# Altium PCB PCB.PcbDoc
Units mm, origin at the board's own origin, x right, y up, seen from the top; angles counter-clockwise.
Board outline 107.6 x 53.34 mm, 4 copper layers (TOP, INNER1, INNER2, BOTTOM), stack 1.569 mm thick; 10 components, 91 nets, 221 pads, 142 vias.
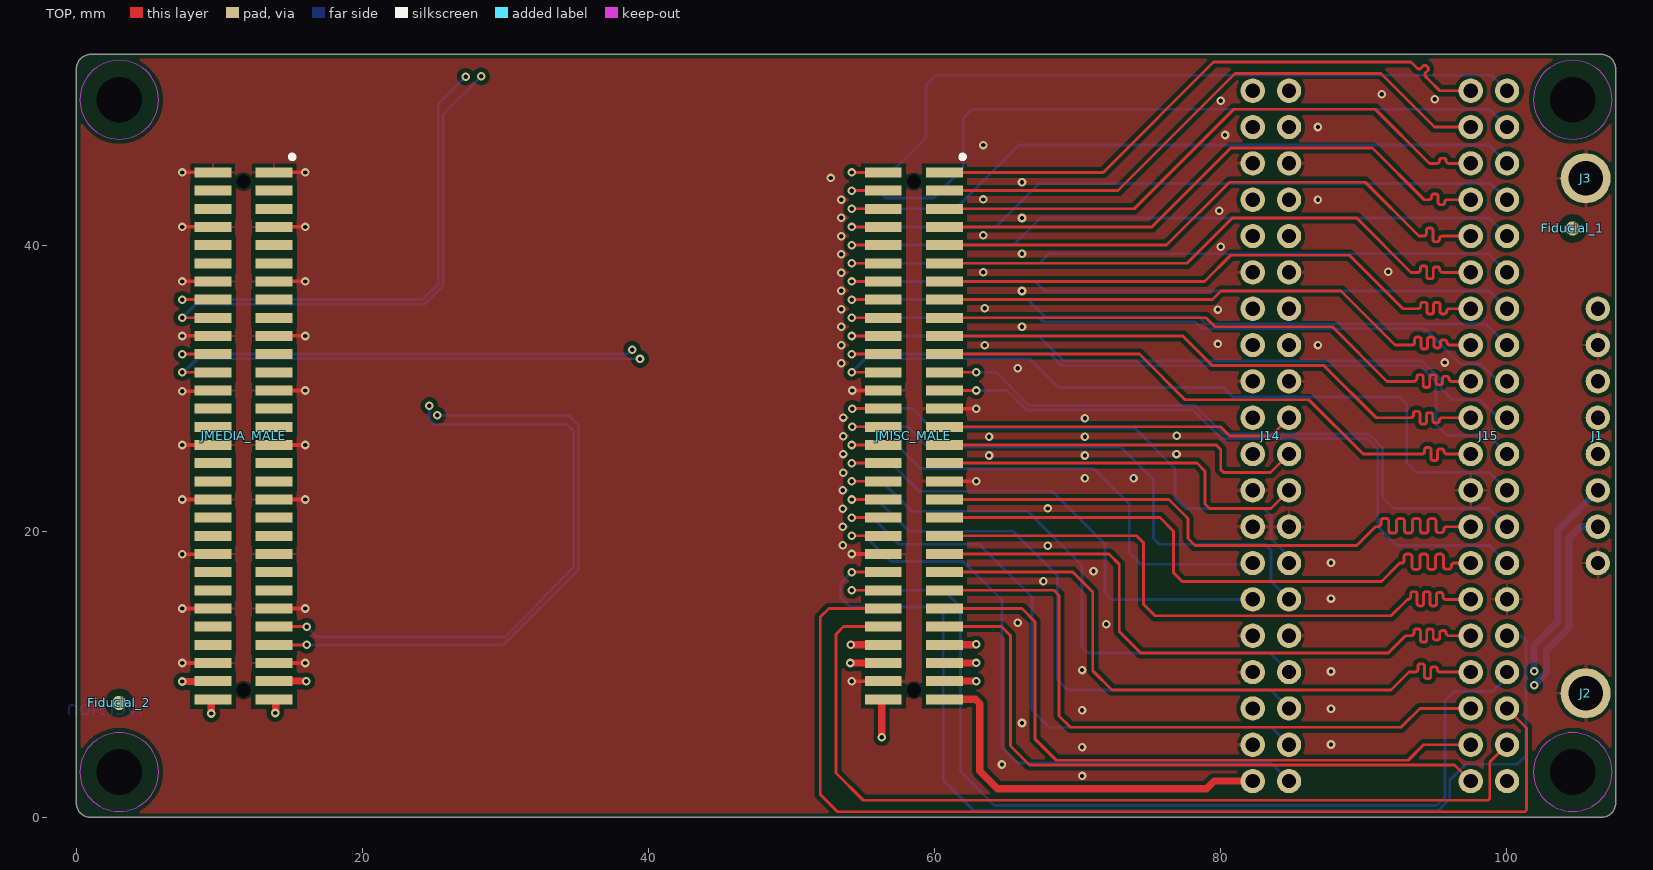
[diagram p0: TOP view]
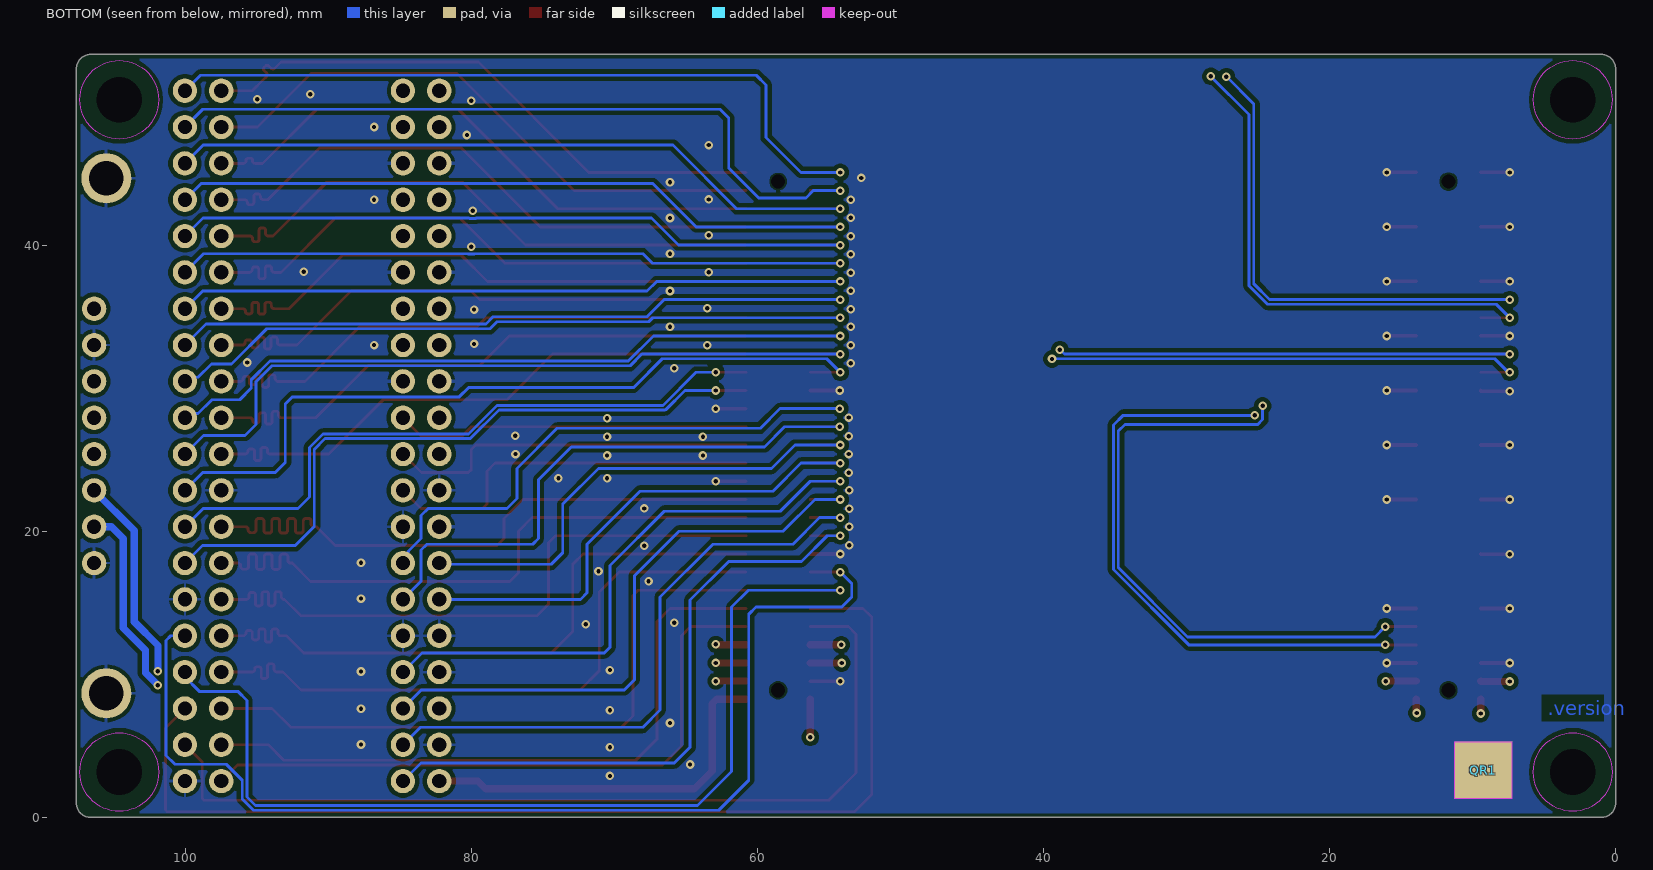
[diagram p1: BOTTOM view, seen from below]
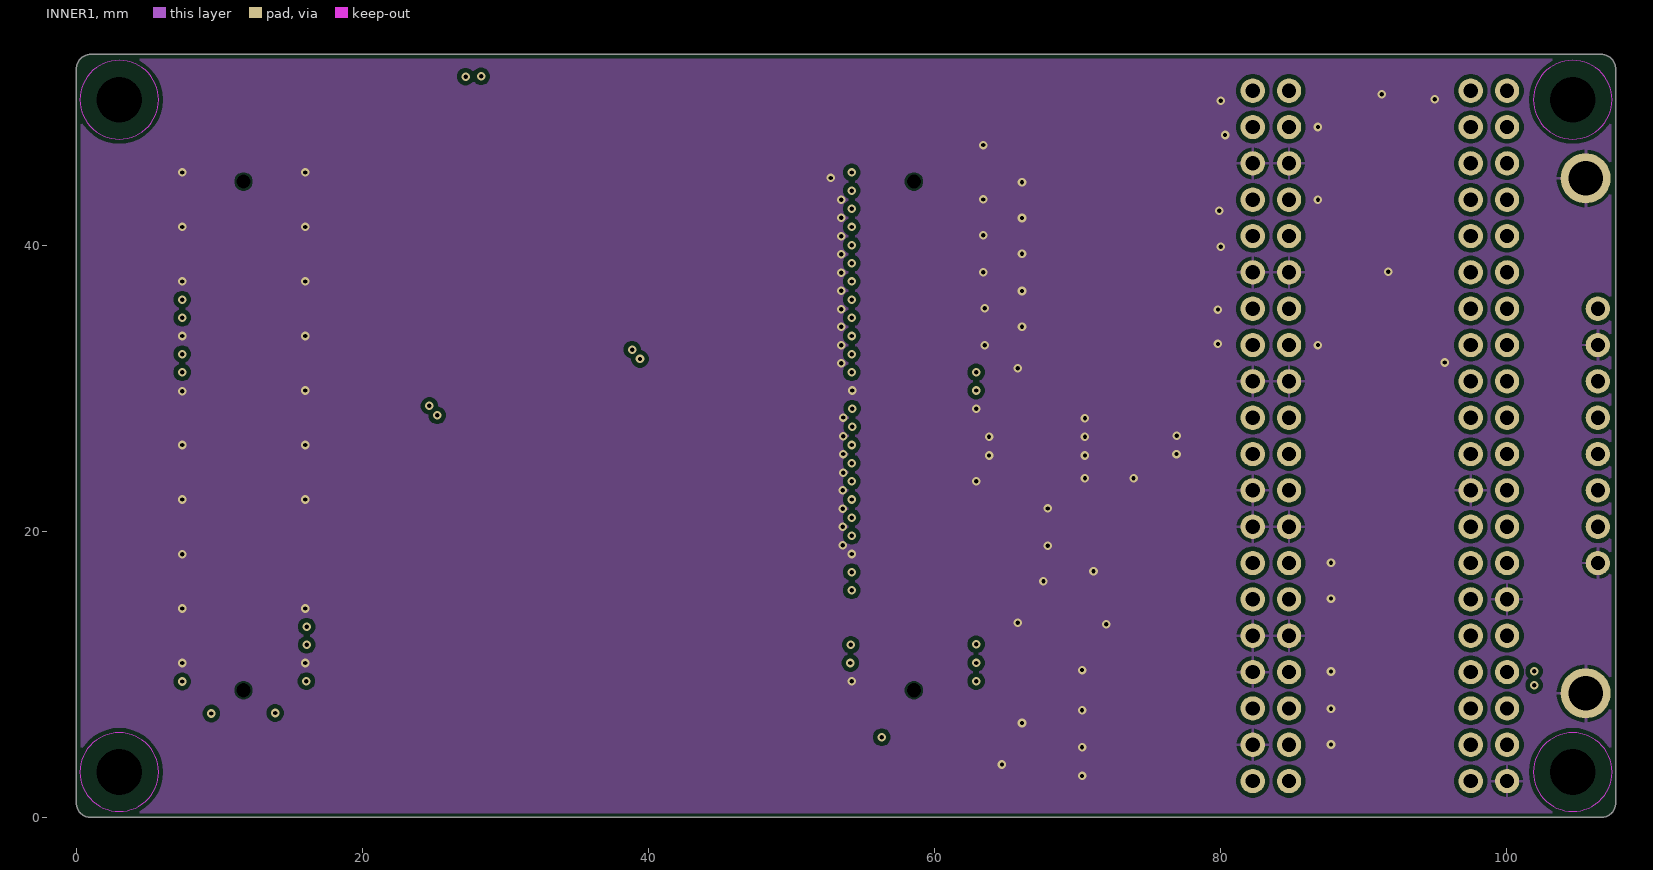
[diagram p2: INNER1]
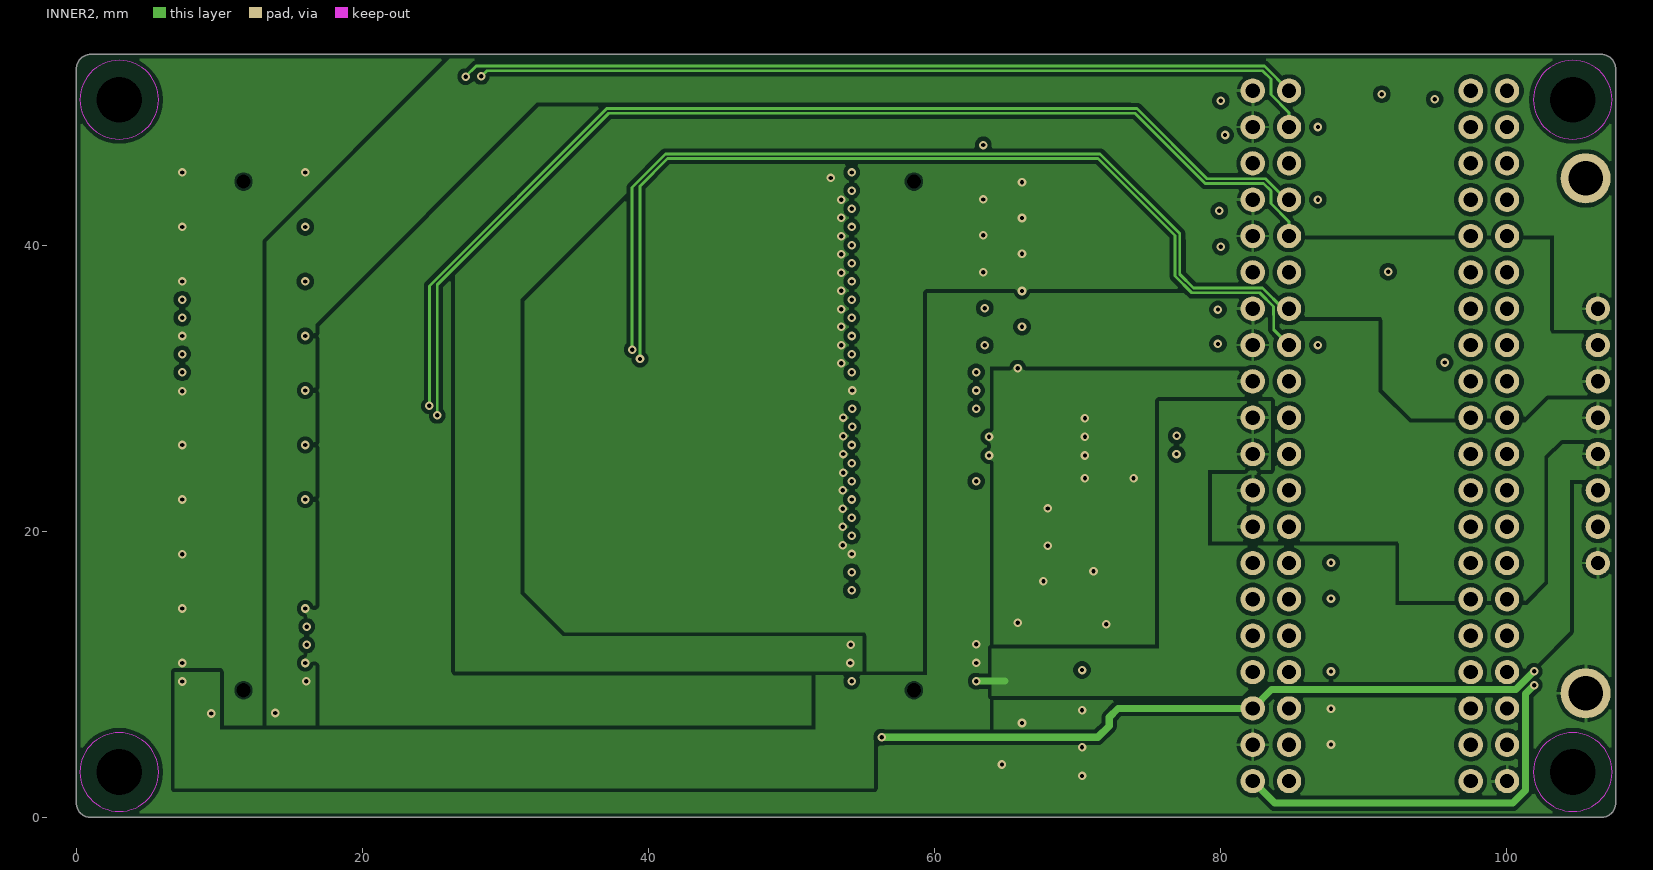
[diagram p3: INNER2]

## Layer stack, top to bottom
Top Solder: solder mask 0.0254, SM-003, Dk 4
TOP: signal copper 0.035
Dielectric 1: prepreg 0.0994, PP-014, Dk 4.2
INNER1: signal copper 0.0175
Dielectric2: core 1.265, FR-4, Dk 4.8
INNER2: signal copper 0.0175
Dielectric3: prepreg 0.0994, PP-014, Dk 4.2
BOTTOM: signal copper 0.035
Bottom Solder: solder mask 0.0254, SM-003, Dk 4

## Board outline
0,1 0,52.34 cw(c1,52.34) 1,53.34 106.6,53.34 cw(c106.6,52.34) 107.6,52.34 107.6,1 cw(c106.6,1) 106.6,0 1,0 cw(c1,1)

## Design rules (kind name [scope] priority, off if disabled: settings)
BoardOutlineClearance Silks [(OnLayer('Top Overlay') OR OnLayer('Bottom Overlay'))] p1: gap=0 ignorepadtopadclearanceinfootprint=FALSE
BoardOutlineClearance [All] p2: gap=0.3 ignorepadtopadclearanceinfootprint=FALSE
Clearance COPPER_0.3mm [All] p1: gap=0.127 ignorepadtopadclearanceinfootprint=FALSE except(0.3: Arc-Fill Arc-Poly Arc-Region Track-Fill Track-Poly Track-Region SMDPad-Fill SMDPad-Poly SMDPad-Region THPad-Fill THPad-Poly THPad-Region Via-Fill Via-Poly Via-Region Fill-Fill Fill-Poly Fill-Region Poly-Poly Poly-Region Region-Region)
Clearance "Generic clearance 0.127mm" [All] p2: gap=0.127 ignorepadtopadclearanceinfootprint=FALSE
ComponentClearance [All] p1: gap=0.2 collisioncheckmode=3 verticalgap=0 showdistances=TRUE
DiffPairsRouting DSI_100R [InDifferentialPairClass('DSI')] p1: maxlimit=0.36 minlimit=0.21 mostfreqgap=0.36 toplayer_maxgap=0.21 toplayer_prefgap=0.21 toplayer_minwidth=0.18 toplayer_maxwidth=0.18 toplayer_prefwidth=0.18 midlayer1_mingap=0.36 midlayer1_minwidth=0.127 midlayer1_maxwidth=0.127 midlayer1_prefwidth=0.127 midlayer2_mingap=0.36 midlayer2_minwidth=0.127 midlayer2_maxwidth=0.127 midlayer2_prefwidth=0.127 bottomlayer_maxgap=0.21 bottomlayer_prefgap=0.21 bottomlayer_minwidth=0.18 bottomlayer_maxwidth=0.18 bottomlayer_prefwidth=0.18 impedanceprofiledriven=TRUE impedanceprofileid={F22B831B-72FA-4BC6-B015-EECE9AC290C8} impedanceprofilevalue=100.000000 maxuncoupledlength=12.7
Height [All] p1: minheight=0 maxheight=30 prefheight=12.7
HoleSize [All] p1: absolutevalues=TRUE maxlimit=30 minlimit=0.3 maxpercent=80.000 minpercent=20.000
HoleToHoleClearance [All] p1: gap=0.25 allowstackedmicrovias=FALSE
MatchedLengths MatchedLengths_SE0 [InNetClass('SE0_Lines')] p1: tolerance=0.15 checknetsindiffpair=FALSE checkdiffpairvsdiffpair=TRUE checkxsignals=TRUE checkothers=TRUE
MatchedLengths MatchedLengths_PSSI [InNetClass('PSSI_Lines')] p2: tolerance=0.15 checknetsindiffpair=FALSE checkdiffpairvsdiffpair=TRUE checkxsignals=TRUE checkothers=TRUE
MatchedLengths DSI_delay_pairs [InDifferentialPairClass('DSI')] p3: tolerance=25.4 checknetsindiffpair=TRUE checkdiffpairvsdiffpair=FALSE checkxsignals=FALSE checkothers=FALSE usedelayunits=TRUE delaytolerance=5.000000
MatchedLengths DSI_delay_group [InDifferentialPairClass('DSI')] p4: tolerance=25.4 checknetsindiffpair=FALSE checkdiffpairvsdiffpair=TRUE checkxsignals=TRUE checkothers=TRUE usedelayunits=TRUE delaytolerance=5.000000
MinimumAnnularRing Fixingpins [(ObjectKind = 'Pad') And (Name = 'Free-FIXING')] p1: minimumring=0
MinimumAnnularRing [All] p2: minimumring=0.15
PlaneConnect [All] p1: pad.planeconnectstyle=Relief pad.reliefexpansion=0.508 pad.reliefentries=4 pad.reliefconductorwidth=0.254 pad.reliefairgap=0.254 via.planeconnectstyle=Direct via.reliefexpansion=0.508 via.reliefentries=4 via.reliefconductorwidth=0.254 via.reliefairgap=0.254
PolygonConnect QR_POLY [(ObjectKind = 'Pad') And (Name = 'QR1-PAD')] p1: connectstyle=Direct reliefconductorwidth=0.254 reliefentries=4 polygonreliefangle="90 Angle" airgapwidth=0.254
PolygonConnect [All] p2: thpad.connectstyle=Relief thpad.reliefconductorwidth=0.2 thpad.reliefentries=4 thpad.polygonreliefangle="90 Angle" thpad.airgapwidth=0.254 smdpad.connectstyle=Relief smdpad.reliefconductorwidth=0.2 smdpad.reliefentries=4 smdpad.polygonreliefangle="90 Angle" smdpad.airgapwidth=0.254 via.connectstyle=Direct via.reliefconductorwidth=0.254 via.reliefentries=4 via.polygonreliefangle="90 Angle" via.airgapwidth=0.254
ReturnPath ReturnPath_100R [InNetClass('IMPEDANCE_100R')] p1: impedanceprofileid={A0C224CA-506F-4870-9C4E-CE84658735AE} _gaplimit=0 _useantipads=TRUE maxstitchviadistance=1.5
RoutingVias StandardVias [All] p1: holewidth=0.3 width=0.6 viastyle="Through Hole" minholewidth=0.3 minwidth=0.6 maxholewidth=0.3 maxwidth=0.6
SMDToCorner [All] p1: distance=39370
SilkToSilkClearance [All] p1: silktosilkclearance=0.2
SilkToSolderMaskClearance [IsPad] p1: minsilkscreentomaskgap=0.15 clearancetoexposedcopper=TRUE
SolderMaskExpansion VIAtented [IsVia] p1: expansion=0.102 istentingtop=TRUE
SolderMaskExpansion [All] p2: expansion=0.05 istentingtop=FALSE
SupplyNets "Schematic Supply Nets_1" [InNet('+5V')] p1: voltage=0.000
SupplyNets "Schematic Supply Nets_5" [InNet('PWR_3P3V')] p2: voltage=0.000
SupplyNets "Schematic Supply Nets_4" [InNet('DC_IN')] p3: voltage=0.000
SupplyNets "Schematic Supply Nets" [InNet('VCC_PX3_1P8')] p4: voltage=0.000
SupplyNets "Schematic Supply Nets_7" [InNet('VCOIN')] p5: voltage=0.000
SupplyNets "Schematic Supply Nets_3" [InNet('VBAT')] p6: voltage=0.000
SupplyNets "Schematic Supply Nets_2" [InNet('GND')] p7: voltage=0.000
UnConnectedPin [All] p1:
UnRoutedNet [All] p1: checkbadconnections=TRUE
ViasUnderSMD [All] p1: allowed=FALSE
Width StandardTraces [All] p1: maxlimit=5 minlimit=0.127 preferedwidth=0.15
21 further rules are at their usual default settings.

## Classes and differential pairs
net class SE0_Lines: NetJ15_25 NetJ15_27 NetJ15_29 NetJ15_31 NetJ15_33 NetJ15_35
net class PSSI_Lines: NetJ15_1 NetJ15_3 NetJ15_5 NetJ15_7 NetJ15_9 NetJ15_11 NetJ15_13 NetJ15_15 NetJ15_17 NetJ15_19 NetJ15_21
component class U_HEADERS: J1 J14 J15
differential pair class DSI: DSI_CLK DSI_D0 DSI_D1 DSI_D2 DSI_D3
component class U_HEADERS_IMOLA_MALE: JMEDIA_MALE JMISC_MALE
differential pair class CSI1: CSI0_CK CSI0_D0 CSI0_D1 CSI0_D2 CSI0_D3
differential pair class CSI0: CSI1_CK CSI1_D0 CSI1_D1 CSI1_D2 CSI1_D3
net class IMPEDANCE_100R: CSI0_CK_N CSI0_CK_P CSI0_D0_N CSI0_D0_P CSI0_D1_N CSI0_D1_P CSI0_D2_N CSI0_D2_P CSI0_D3_N CSI0_D3_P CSI1_CK_N CSI1_CK_P CSI1_D0_N CSI1_D0_P CSI1_D1_N CSI1_D1_P CSI1_D2_N CSI1_D2_P CSI1_D3_N CSI1_D3_P DSI_CLK_N DSI_CLK_P DSI_D0_N DSI_D0_P DSI_D1_N DSI_D1_P DSI_D2_N DSI_D2_P DSI_D3_N DSI_D3_P
component class TOP: Fiducial_1 Fiducial_2 J2 J3 QR1
differential pair DSI_D3: +DSI_D3_P -DSI_D3_N
differential pair DSI_D2: +DSI_D0_P -DSI_D0_N
differential pair DSI_D1: +DSI_CLK_P -DSI_CLK_N
differential pair DSI_D0: +DSI_D2_P -DSI_D2_N
differential pair DSI_CLK: +DSI_D1_P -DSI_D1_N
differential pair CSI1_D3: +CSI0_D1_P -CSI0_D1_N
differential pair CSI1_D2: +CSI0_CK_P -CSI0_CK_N
differential pair CSI1_D1: +CSI0_D3_P -CSI0_D3_N
differential pair CSI1_D0: +CSI1_D0_P -CSI1_D0_N
differential pair CSI1_CK: +CSI0_D2_P -CSI0_D2_N
differential pair CSI0_D3: +CSI1_D1_P -CSI1_D1_N
differential pair CSI0_D2: +CSI1_CK_P -CSI1_CK_N
differential pair CSI0_D1: +CSI1_D3_P -CSI1_D3_N
differential pair CSI0_D0: +CSI0_D0_P -CSI0_D0_N
differential pair CSI0_CK: +CSI1_D2_P -CSI1_D2_N

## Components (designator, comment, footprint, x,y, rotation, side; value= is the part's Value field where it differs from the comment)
Fiducial_1 "Fiducial mark 1mm with 2mm solder" "Fiducial mark 1mm with circle-Footprint-1" 104.6,41.17 r90 top
Fiducial_2 "Fiducial mark 1mm with 2mm solder" "Fiducial mark 1mm with circle-Footprint-1" 3,8 r90 top
J1 "HEADER TH 2.54mm VERT. 1x008POS" "PIN HEADER 2.54mm VERT. 1x8POS" 106.36,26.67 r270 top
J2 "1502-2" 1502-2 105.5,8.67 r0 top
J3 "1502-2" 1502-2 105.5,44.67 r0 top
J14 "PH2-40-UA" "PIN HEADER 2.54mm VERT. 2x20POS" 83.5,26.67 r270 top locked
J15 "PH2-40-UA" "PIN HEADER 2.54mm VERT. 2x20POS" 98.74,26.67 r270 top locked
JMEDIA_MALE "GPEC212-3002A011C1AF" GPEC212-3002A011C1AF 11.684,26.67 r270 top
JMISC_MALE "GPEC212-3002A011C1AF" GPEC212-3002A011C1AF 58.547,26.67 r270 top
QR1 "QR CODE 4x4mm" "QR CODE 4x4mm" 9.25,3.3 r180 bottom locked

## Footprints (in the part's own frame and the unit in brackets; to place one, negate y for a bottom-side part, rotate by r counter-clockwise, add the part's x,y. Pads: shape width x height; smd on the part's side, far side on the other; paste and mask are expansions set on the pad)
1502-2 [mm]
  round 3.5 hole 2.4 paste-2539.97 mask+0.102: 1(0,0)
  body extent -1.58,-1.59 1.58,1.59, height 5.63
"Fiducial mark 1mm with circle-Footprint-1" [mm]
  round 1 smd paste-10 mask+0.5: 1(0,0)
  TOP pour cut-out: 0,1 0.383,0.924 0.707,0.707 0.924,0.383 1,0 1,0 0.924,-0.383 0.707,-0.707 0.383,-0.924 0,-1 0,-1 -0.383,-0.924 -0.707,-0.707 -0.924,-0.383 -1,0 -1,0 -0.924,0.383 -0.707,0.707 -0.383,0.924 0,1
GPEC212-3002A011C1AF [mm]
  rect 0.7x2.57 smd mask+0.1: 1(-18.415,2.135) 2(-18.415,-2.135) 3(-17.145,2.135) 4(-17.145,-2.135) 5(-15.875,2.135) 6(-15.875,-2.135) 7(-14.605,2.135) 8(-14.605,-2.135) 9(-13.335,2.135) 10(-13.335,-2.135) 11(-12.065,2.135) 12(-12.065,-2.135) 13(-10.795,2.135) 14(-10.795,-2.135) 15(-9.525,2.135) 16(-9.525,-2.135) 17(-8.255,2.135) 18(-8.255,-2.135) 19(-6.985,2.135) 20(-6.985,-2.135) 21(-5.715,2.135) 22(-5.715,-2.135) 23(-4.445,2.135) 24(-4.445,-2.135) 25(-3.175,2.135) 26(-3.175,-2.135) 27(-1.905,2.135) 28(-1.905,-2.135) 29(-0.635,2.135) 30(-0.635,-2.135) 31(0.635,2.135) 32(0.635,-2.135) 33(1.905,2.135) 34(1.905,-2.135) 35(3.175,2.135) 36(3.175,-2.135) 37(4.445,2.135) 38(4.445,-2.135) 39(5.715,2.135) 40(5.715,-2.135) 41(6.985,2.135) 42(6.985,-2.135) 43(8.255,2.135) 44(8.255,-2.135) 45(9.525,2.135) 46(9.525,-2.135) 47(10.795,2.135) 48(10.795,-2.135) 49(12.065,2.135) 50(12.065,-2.135) 51(13.335,2.135) 52(13.335,-2.135) 53(14.605,2.135) 54(14.605,-2.135) 55(15.875,2.135) 56(15.875,-2.135) 57(17.145,2.135) 58(17.145,-2.135) 59(18.415,2.135) 60(18.415,-2.135)
  silkscreen extent -19.55,3.35 -19.45,3.45, body extent -19.05,-2.92 19.05,2.92, height 5.97
"PIN HEADER 2.54mm VERT. 1x8POS" [mm]
  round 1.7 hole 1 mask+0.1: 1(-8.89,0) 2(-6.35,0) 3(-3.81,0) 4(-1.27,0) 5(1.27,0) 6(3.81,0) 7(6.35,0) 8(8.89,0)
"PIN HEADER 2.54mm VERT. 2x20POS" [mm]
  round 1.7 hole 1: 1(-24.13,-1.27) 2(-24.13,1.27) 3(-21.59,-1.27) 4(-21.59,1.27) 5(-19.05,-1.27) 6(-19.05,1.27) 7(-16.51,-1.27) 8(-16.51,1.27) 9(-13.97,-1.27) 10(-13.97,1.27) 11(-11.43,-1.27) 12(-11.43,1.27) 13(-8.89,-1.27) 14(-8.89,1.27) 15(-6.35,-1.27) 16(-6.35,1.27) 17(-3.81,-1.27) 18(-3.81,1.27) 19(-1.27,-1.27) 20(-1.27,1.27) 21(1.27,-1.27) 22(1.27,1.27) 23(3.81,-1.27) 24(3.81,1.27) 25(6.35,-1.27) 26(6.35,1.27) 27(8.89,-1.27) 28(8.89,1.27) 29(11.43,-1.27) 30(11.43,1.27) 31(13.97,-1.27) 32(13.97,1.27) 33(16.51,-1.27) 34(16.51,1.27) 35(19.05,-1.27) 36(19.05,1.27) 37(21.59,-1.27) 38(21.59,1.27) 39(24.13,-1.27) 40(24.13,1.27)
  body extent -25.4,-2.54 25.4,2.54, height 9.5
"QR CODE 4x4mm" [mm]
  rect 4x4 smd paste-2539.97 mask+0.1: PAD(0,0)
  TOP keep-out region: -2,2 2,2 2,-2 -2,-2

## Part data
Fiducial_1 Fiducial_2: library part UT0024-A.6
J1: library part J0171-A.4
J2 J3: library part J0379-A.2, "Turret Connector TH 5,56mm lenght", Manufacturer="Keystone Electronics"
J14 J15: library part J0326-A.4, "HEADER TH 2.54mm VERT. MALE 2x20POS", Manufacturer="Adam Tech"
JMEDIA_MALE JMISC_MALE: library part J0568-A.3, "CONN HEADER MALE VERTICAL SMD 1.27mm 2x30 POS lead heigth 3.5mm", Manufacturer=Greenconn
QR1: library part QR-0001-A.5, "QR CODE 4x4mm on layer 34 (This is not a component)", Manufacturer="This is not a component"

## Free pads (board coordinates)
  round 0.6 hole 1: FIXING(11.684,8.89) FIXING(11.684,44.45) FIXING(58.547,8.89) FIXING(58.547,44.45)
  oval 2.9x3 hole 3.2 unplated paste-2539.97 mask+1.4: MH(3,3.17) MH(3,50.17) MH(104.6,3.17) MH(104.6,50.17)

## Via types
v1: diameter 0.6, hole 0.3, TOP to BOTTOM, tented both sides, 142 vias

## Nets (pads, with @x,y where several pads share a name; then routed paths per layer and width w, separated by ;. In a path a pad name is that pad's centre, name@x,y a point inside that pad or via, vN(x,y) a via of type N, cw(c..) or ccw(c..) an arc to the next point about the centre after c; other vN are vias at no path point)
+5V: J1.3 J14.7 J14.9 JMISC_MALE.54 JMISC_MALE.56 | length 4.4
  TOP w0.5: v1(54.105,10.795) JMISC_MALE.56@56.297,10.795 ; v1(54.135,12.065) JMISC_MALE.54@56.297,12.065
CSI0_CK_N: JMEDIA_MALE.33
CSI0_CK_P: JMEDIA_MALE.35
CSI0_D0_N: JMEDIA_MALE.21
CSI0_D0_P: JMEDIA_MALE.23
CSI0_D1_N: JMEDIA_MALE.27
CSI0_D1_P: JMEDIA_MALE.29
CSI0_D2_N: JMEDIA_MALE.39
CSI0_D2_P: JMEDIA_MALE.41
CSI0_D3_N: JMEDIA_MALE.45
CSI0_D3_P: JMEDIA_MALE.47
CSI1_CK_N: JMEDIA_MALE.42
CSI1_CK_P: JMEDIA_MALE.40
CSI1_D0_N: JMEDIA_MALE.54
CSI1_D0_P: JMEDIA_MALE.52
CSI1_D1_N: JMEDIA_MALE.48
CSI1_D1_P: JMEDIA_MALE.46
CSI1_D2_N: JMEDIA_MALE.36
CSI1_D2_P: JMEDIA_MALE.34
CSI1_D3_N: JMEDIA_MALE.30
CSI1_D3_P: JMEDIA_MALE.28
DC_IN: J1.1 J14.1 J14.3 JMEDIA_MALE.57 JMEDIA_MALE.59 | length 3.1
  TOP w0.5: v1(13.9,7.3) 13.9,7.327 13.934,7.361 JMEDIA_MALE.59@13.934,8.255 ; JMEDIA_MALE.57@13.934,9.525 v1(16.075,9.525)
DSI_CLK_N: JMEDIA_MALE.3
DSI_CLK_P: JMEDIA_MALE.5
DSI_D0_N: JMEDIA_MALE.12
DSI_D0_P: JMEDIA_MALE.10
DSI_D1_N: JMEDIA_MALE.6
DSI_D1_P: JMEDIA_MALE.4
DSI_D2_N: JMEDIA_MALE.9
DSI_D2_P: JMEDIA_MALE.11
DSI_D3_N: JMEDIA_MALE.15
DSI_D3_P: JMEDIA_MALE.17
GND: J1.2 J1.8 J2.1 J3.1 J14.5 J14.6 J14.11 J14.12 J14.17 J14.18 J14.23 J14.25 J14.26 J14.31 J14.32 J14.33 J14.37 J15.23 J15.30 J15.40 JMEDIA_MALE.1 JMEDIA_MALE.2 JMEDIA_MALE.7 JMEDIA_MALE.8 JMEDIA_MALE.13 JMEDIA_MALE.14 JMEDIA_MALE.19 JMEDIA_MALE.20 JMEDIA_MALE.25 JMEDIA_MALE.26 JMEDIA_MALE.31 JMEDIA_MALE.32 JMEDIA_MALE.37 JMEDIA_MALE.38 JMEDIA_MALE.43 JMEDIA_MALE.44 JMEDIA_MALE.49 JMEDIA_MALE.50 JMEDIA_MALE.55 JMEDIA_MALE.56 JMISC_MALE.26 JMISC_MALE.27 JMISC_MALE.35 JMISC_MALE.44 JMISC_MALE.58 QR1.PAD | length 49.4
  TOP w0.25: v1(7.4,10.795) JMEDIA_MALE.56@9.434,10.795 ; v1(7.4,14.605) JMEDIA_MALE.50@9.434,14.605 ; v1(7.4,18.4) 9.434,18.4 JMEDIA_MALE.44@9.434,18.415 ; v1(7.4,22.225) JMEDIA_MALE.38@9.434,22.225 ; v1(7.4,26.035) JMEDIA_MALE.32@9.434,26.035 ; v1(7.4,29.8) 9.434,29.8 JMEDIA_MALE.26@9.434,29.845 ; v1(7.4,33.655) JMEDIA_MALE.20@9.434,33.655 ; v1(7.4,37.465) JMEDIA_MALE.14@9.434,37.465 ; v1(7.4,41.275) JMEDIA_MALE.8@9.434,41.275 ; v1(7.4,45.085) JMEDIA_MALE.2@9.434,45.085 ; JMEDIA_MALE.55@13.934,10.795 v1(16,10.795) ; JMEDIA_MALE.49@13.934,14.605 v1(16,14.605) ; JMEDIA_MALE.37@13.934,22.225 v1(16,22.225) ; JMEDIA_MALE.31@13.934,26.035 v1(16,26.035) ; JMEDIA_MALE.25@13.934,29.845 v1(16,29.845) ; JMEDIA_MALE.19@13.934,33.655 v1(16,33.655) ; JMEDIA_MALE.13@13.934,37.465 v1(16,37.465) ; JMEDIA_MALE.7@13.934,41.275 v1(16,41.275) ; JMEDIA_MALE.1@13.934,45.085 v1(16,45.085) ; v1(54.2,9.525) JMISC_MALE.58@56.297,9.525 ; v1(54.2,18.415) JMISC_MALE.44@56.297,18.415 ; v1(54.246,29.845) JMISC_MALE.26@56.297,29.845 ; JMISC_MALE.35@60.797,23.495 v1(62.9,23.495) ; JMISC_MALE.27@60.797,28.575 v1(62.9,28.575)
  other v1: 70.3,2.9 64.7,3.7 70.3,4.9 87.7,5.1 66.1,6.6 70.3,7.5 87.7,7.6 87.7,10.2 70.3,10.3 72,13.5 65.8,13.6 87.7,15.3 67.6,16.5 71.1,17.2 87.7,17.8 67.9,19 53.575,19.025 53.575,20.325 53.575,21.575 67.9,21.6 53.575,22.875 70.5,23.7 73.9,23.7 53.6,24.1 63.8,25.3 70.5,25.3 53.6,25.4 76.9,25.4 63.8,26.6 70.5,26.6 53.6,26.65 76.917,26.67 70.5,27.9 53.6,27.95 65.8,31.4 53.475,31.75 95.65,31.8 53.475,33 63.5,33 86.788,33.02 79.8,33.1 53.475,34.3 66.1,34.3 79.8,35.5 53.475,35.525 63.5,35.6 66.1,36.8 53.475,36.825 53.475,38.075 63.4,38.1 91.7,38.15 53.475,39.375 66.1,39.4 80,39.9 53.475,40.625 63.4,40.7 66.1,41.9 53.475,41.925 79.9,42.4 53.475,43.175 86.788,43.18 63.4,43.2 66.1,44.4 52.725,44.7 63.4,47 80.3,47.7 86.788,48.26 80,50.1 94.95,50.2 91.25,50.55
GPIO_22: J14.10 JMEDIA_MALE.53 | length 121.9
  TOP w0.2: JMEDIA_MALE.53@13.934,12.065 v1(16.1,12.065)
  INNER2 w0.2: v1(25.225,28.107) 25.225,37.238 37.212,49.225 74,49.225 78.909,44.316 82.984,44.316 83.5,43.8 83.5,42.909 84.77,41.639 J14.10
  BOTTOM w0.2: v1(16.1,12.065) 29.84,12.065 35.1,17.325 35.1,27.425 34.418,28.107 v1(25.225,28.107)
GPIO_23: J14.8 JMEDIA_MALE.51 | length 120.3
  TOP w0.2: JMEDIA_MALE.51@13.934,13.335 v1(16.1,13.335)
  INNER2 w0.2: v1(24.676,28.767) 24.676,37.151 37.077,49.552 74.135,49.552 79.044,44.643 83.119,44.643 84.582,43.18 J14.8
  BOTTOM w0.2: v1(16.1,13.335) 16.817,12.618 29.931,12.618 34.773,17.46 34.773,27.01 34.308,27.475 25.021,27.475 24.676,27.819 v1(24.676,28.767)
GPIO_29: J14.14 JMEDIA_MALE.22 | length 98
  TOP w0.2: v1(7.4,32.385) JMEDIA_MALE.22@9.434,32.385
  INNER2 w0.2: v1(38.85,32.7) 38.85,44.037 41.19,46.377 71.56,46.377 77.127,40.81 77.127,37.973 78.1,37 82.924,37 84.364,35.56 J14.14
  BOTTOM w0.2: v1(7.4,32.385) 38.535,32.385 v1(38.85,32.7)
GPIO_30: J14.16 JMEDIA_MALE.24 | length 100.7
  TOP w0.2: v1(7.4,31.115) JMEDIA_MALE.24@9.434,31.115
  INNER2 w0.2: v1(39.4,32.05) 39.4,44.125 41.325,46.05 71.425,46.05 76.8,40.675 76.8,37.838 77.965,36.673 82.727,36.673 83.693,35.707 83.693,35.114 83.698,35.109 83.698,34.092 J14.16
  BOTTOM w0.2: v1(7.4,31.115) 7.508,31.115 8.451,32.058 39.392,32.058 v1(39.4,32.05)
NetJ14_2: J14.2 JMEDIA_MALE.16 | length 94.2
  TOP w0.2: v1(7.4,36.195) JMEDIA_MALE.16@9.434,36.195
  INNER2 w0.2: v1(27.21,51.785) 27.95,52.525 83.045,52.525 J14.2
  BOTTOM w0.2: v1(7.4,36.195) 24.195,36.195 25.3,37.3 25.3,49.875 v1(27.21,51.785)
NetJ14_4: J14.4 JMEDIA_MALE.18 | length 96.5
  TOP w0.2: v1(7.4,34.925) JMEDIA_MALE.18@9.434,34.925
  INNER1 w0.2: v1(7.4,34.925) v1@7.5,34.925
  INNER2 w0.2: v1(28.3,51.8) 28.698,52.198 82.91,52.198 83.5,51.608 83.5,50.529 84.77,49.259 J14.4
  BOTTOM w0.2: v1(7.4,34.925) 8.343,35.868 24.331,35.868 25.627,37.165 25.627,49.127 v1(28.3,51.8)
NetJ14_20: J14.20 JMISC_MALE.29 | length 24.8
  TOP w0.2: JMISC_MALE.29@60.797,27.305 79.988,27.305 80.623,26.67 83.5,26.67 J14.20
NetJ14_22: J14.22 JMISC_MALE.31 | length 26.1
  TOP w0.2: JMISC_MALE.31@60.797,26.035 79.678,26.035 80,25.713 80,24.3 80.2,24.1 83.47,24.1 J14.22
NetJ14_24: J14.24 JMISC_MALE.33 | length 27.4
  TOP w0.2: JMISC_MALE.33@60.797,24.765 78.335,24.765 78.9,24.2 78.9,21.9 79.2,21.6 83.51,21.6 J14.24 J14.24@84.77,22.57
NetJ14_27: J14.27 JMISC_MALE.32 | length 35.6
  TOP w0.2: v1(54.2,26.035) JMISC_MALE.32@56.297,26.035
  BOTTOM w0.2: v1(54.2,26.035) 57.365,26.035 59,24.4 71.1,24.4 73.6,21.9 73.6,18.5 74.4,17.7 82.15,17.7 J14.27
NetJ14_28: J14.28 JMISC_MALE.28 | length 39.5
  TOP w0.2: v1(54.231,28.575) JMISC_MALE.28@56.297,28.575
  BOTTOM w0.2: v1(54.231,28.575) 58.412,28.575 59.787,27.2 74,27.2 76.8,24.4 76.8,22.3 77.5,21.6 83,21.6 83.5,21.1 83.5,19.5 84.382,18.618 84.382,18.574 84.77,18.186 J14.28
NetJ14_29: J14.29 JMISC_MALE.34 | length 36.1
  TOP w0.2: v1(54.2,24.765) JMISC_MALE.34@56.297,24.765
  BOTTOM w0.2: v1(54.2,24.765) 56.935,24.765 58.9,22.8 68.2,22.8 71.9,19.1 71.9,15.7 72.36,15.24 J14.29
NetJ14_30: J14.30 JMISC_MALE.30 | length 41.3
  TOP w0.2: v1(54.231,27.305) JMISC_MALE.30@56.297,27.305
  BOTTOM w0.2: v1(54.231,27.305) 58.095,27.305 59.5,25.9 73,25.9 75.3,23.6 75.3,19.5 75.7,19.1 83.1,19.1 83.5,18.7 83.5,16.51 J14.30
NetJ14_34: J14.34 JMISC_MALE.36 | length 41.5
  TOP w0.2: v1(54.2,23.495) JMISC_MALE.36@56.297,23.495
  BOTTOM w0.2: v1(54.2,23.495) 56.305,23.495 58.4,21.4 66.5,21.4 70.3,17.6 70.3,11.9 70.7,11.5 83.43,11.5 J14.34
NetJ14_36: J14.36 JMISC_MALE.38 | length 43
  TOP w0.2: v1(54.2,22.225) JMISC_MALE.38@56.297,22.225
  BOTTOM w0.2: v1(54.2,22.225) 55.975,22.225 58.2,20 65.475,20 68.58,16.895 68.58,9.62 69.3,8.9 83.49,8.9 J14.36
NetJ14_38: J14.38 JMISC_MALE.40 | length 43.9
  TOP w0.2: v1(54.2,20.955) JMISC_MALE.40@56.297,20.955
  BOTTOM w0.2: v1(54.2,20.955) 55.645,20.955 57.5,19.1 63.1,19.1 66.8,15.4 66.8,7.5 68,6.3 83.55,6.3 J14.38
NetJ14_40: J14.40 JMISC_MALE.42 | length 45.8
  TOP w0.2: v1(54.2,19.685) JMISC_MALE.42@56.297,19.685
  BOTTOM w0.2: v1(54.2,19.685) 55.115,19.685 56.9,17.9 62,17.9 64.7,15.2 64.7,4.9 65.8,3.8 83.51,3.8 J14.40
NetJ15_1: J15.1 JMISC_MALE.1 | length 41.5
  TOP w0.2: JMISC_MALE.1@60.797,45.085 65.1,45.085 71.785,45.085 79.5,52.8 93.3,52.8 93.65,52.45 93.721,52.379 ccw(c93.862,52.521) 94.004,52.379 94.156,52.532 cw(c94.268,52.421) 94.379,52.532 94.475,52.437 cw(c94.363,52.325) 94.475,52.214 94.322,52.061 ccw(c94.463,51.92) 94.322,51.778 94.509,51.591 94.579,51.521 95.3,50.8 J15.1
NetJ15_2: J15.2 JMISC_MALE.2 | length 53.3
  TOP w0.2: v1(54.2,45.085) JMISC_MALE.2@56.297,45.085
  BOTTOM w0.2: v1(54.2,45.085) 56.954,45.085 59.4,47.531 59.4,51.208 60.069,51.877 98.933,51.877 J15.2
NetJ15_3: J15.3 JMISC_MALE.3 | length 41.6
  TOP w0.2: JMISC_MALE.3@60.797,43.815 72.815,43.815 81,52 91.2,52 94.94,48.26 J15.3
NetJ15_4: J15.4 JMISC_MALE.4 | length 53.3
  TOP w0.2: v1(54.2,43.815) JMISC_MALE.4@56.297,43.815
  BOTTOM w0.2: v1(54.2,43.815) 56.085,43.815 56.6,43.3 59.9,43.3 62,45.4 62,48.9 62.6,49.5 98.77,49.5 J15.4
NetJ15_5: J15.5 JMISC_MALE.5 | length 41.5
  TOP w0.2: JMISC_MALE.5@60.797,42.545 62.372,42.545 65.3,42.545 73.945,42.545 80.9,49.5 90.8,49.5 94.58,45.72 94.99,45.72 95.09,45.72 ccw(c95.09,45.92) 95.29,45.92 95.29,45.925 cw(c95.448,45.925) 95.448,46.082 95.583,46.082 cw(c95.583,45.925) 95.74,45.925 95.74,45.92 ccw(c95.94,45.92) 95.94,45.72 96.5,45.72 J15.5
NetJ15_6: J15.6 JMISC_MALE.6 | length 50.3
  TOP w0.2: v1(54.2,42.545) JMISC_MALE.6@56.297,42.545
  BOTTOM w0.2: v1(54.2,42.545) 61.445,42.545 65.9,47 98.73,47 J15.6
NetJ15_7: J15.7 JMISC_MALE.7 | length 41.5
  TOP w0.2: JMISC_MALE.7@60.797,41.275 65.25,41.275 67.386,41.275 75.175,41.275 80.697,46.797 90.603,46.797 94.22,43.18 94.44,43.18 94.54,43.18 ccw(c94.54,43.38) 94.74,43.38 94.74,43.426 cw(c94.898,43.426) 94.898,43.583 95.033,43.583 cw(c95.033,43.426) 95.19,43.426 95.19,42.98 ccw(c95.348,42.98) 95.348,42.822 95.483,42.822 ccw(c95.483,42.98) 95.64,42.98 cw(c95.84,42.98) 95.84,43.18 96.5,43.18 J15.7
NetJ15_8: J15.8 JMISC_MALE.8 | length 49.6
  TOP w0.2: v1(54.2,41.275) JMISC_MALE.8@56.297,41.275
  BOTTOM w0.2: v1(54.2,41.275) 64.266,41.275 67.291,44.3 98.89,44.3 J15.8
NetJ15_9: J15.9 JMISC_MALE.9 | length 41.5
  TOP w0.2: JMISC_MALE.9@60.797,40.005 76.205,40.005 80.6,44.4 90.1,44.4 93.86,40.64 94.078,40.64 94.178,40.64 ccw(c94.178,40.84) 94.378,40.84 94.378,41.045 cw(c94.535,41.045) 94.535,41.202 94.67,41.202 cw(c94.67,41.045) 94.828,41.045 94.828,40.395 ccw(c94.985,40.395) 94.985,40.238 95.12,40.238 ccw(c95.12,40.395) 95.278,40.395 95.278,40.44 cw(c95.478,40.44) 95.478,40.64 96.2,40.64 J15.9
NetJ15_10: J15.10 JMISC_MALE.10 | length 49.2
  TOP w0.2: v1(54.2,40.005) JMISC_MALE.10@56.297,40.005
  BOTTOM w0.2: v1(54.2,40.005) 65.505,40.005 67.4,41.9 79.655,41.9 79.682,41.873 80.118,41.873 80.145,41.9 98.75,41.9 J15.10
NetJ15_11: J15.11 JMISC_MALE.11 | length 41.5
  TOP w0.2: JMISC_MALE.11@60.797,38.735 66.165,38.735 69.342,38.735 77.635,38.735 80.8,41.9 89.5,41.9 93.3,38.1 93.65,38.1 93.75,38.1 ccw(c93.75,38.3) 93.95,38.3 93.95,38.393 cw(c94.108,38.393) 94.108,38.55 94.243,38.55 cw(c94.243,38.393) 94.4,38.393 94.4,37.808 ccw(c94.558,37.808) 94.558,37.65 94.693,37.65 ccw(c94.693,37.808) 94.85,37.808 94.85,38.321 cw(c95.008,38.321) 95.008,38.478 95.143,38.478 cw(c95.143,38.321) 95.3,38.321 95.3,38.3 ccw(c95.5,38.3) 95.5,38.1 96.2,38.1 J15.11
NetJ15_12: J15.12 JMISC_MALE.12 | length 48.7
  TOP w0.2: v1(54.2,38.735) JMISC_MALE.12@56.297,38.735
  BOTTOM w0.2: v1(54.2,38.735) 67.335,38.735 68,39.4 79.755,39.4 79.782,39.373 80.218,39.373 80.245,39.4 98.71,39.4 J15.12
NetJ15_13: J15.13 JMISC_MALE.13 | length 41.5
  TOP w0.2: JMISC_MALE.13@60.797,37.465 78.865,37.465 80.7,39.3 89,39.3 92.74,35.56 93.672,35.56 93.773,35.56 ccw(c93.773,35.76) 93.973,35.76 93.973,35.853 cw(c94.13,35.853) 94.13,36.01 94.265,36.01 cw(c94.265,35.853) 94.423,35.853 94.423,35.337 ccw(c94.58,35.337) 94.58,35.179 94.715,35.179 ccw(c94.715,35.337) 94.873,35.337 94.873,35.848 cw(c95.03,35.848) 95.03,36.006 95.165,36.006 cw(c95.165,35.848) 95.323,35.848 95.323,35.36 ccw(c95.48,35.36) 95.48,35.202 95.615,35.202 ccw(c95.615,35.36) 95.773,35.36 cw(c95.973,35.36) 95.973,35.56 96.38,35.56 J15.13
NetJ15_14: J15.14 JMISC_MALE.14 | length 48.7
  TOP w0.2: v1(54.2,37.465) JMISC_MALE.14@56.297,37.465
  BOTTOM w0.2: v1(54.2,37.465) 67.035,37.465 67.7,36.8 98.77,36.8 J15.14
NetJ15_15: J15.15 JMISC_MALE.15 | length 41.5
  TOP w0.2: JMISC_MALE.15@60.797,36.195 79.414,36.195 80.019,36.8 88.4,36.8 92.18,33.02 93.25,33.02 93.35,33.02 ccw(c93.35,33.22) 93.55,33.22 93.55,33.42 cw(c93.708,33.42) 93.708,33.577 93.843,33.577 cw(c93.843,33.42) 94,33.42 94,32.898 ccw(c94.158,32.898) 94.158,32.741 94.293,32.741 ccw(c94.293,32.898) 94.45,32.898 94.45,33.42 cw(c94.607,33.42) 94.607,33.577 94.743,33.577 cw(c94.743,33.42) 94.9,33.42 94.9,32.98 ccw(c95.057,32.98) 95.057,32.823 95.193,32.823 ccw(c95.193,32.98) 95.35,32.98 95.35,33.22 cw(c95.507,33.22) 95.507,33.378 95.643,33.378 cw(c95.643,33.22) 95.8,33.22 ccw(c96,33.22) 96,33.02 96.359,33.02 J15.15
NetJ15_17: J15.17 JMISC_MALE.17 | length 41.5
  TOP w0.2: JMISC_MALE.17@60.797,34.925 78.975,34.925 79.6,34.3 87.8,34.3 91.62,30.48 93.403,30.48 93.503,30.48 ccw(c93.503,30.68) 93.703,30.68 93.703,30.784 cw(c93.86,30.784) 93.86,30.941 93.995,30.941 cw(c93.995,30.784) 94.153,30.784 94.153,30.22 ccw(c94.31,30.22) 94.31,30.062 94.445,30.062 ccw(c94.445,30.22) 94.603,30.22 94.603,30.784 cw(c94.76,30.784) 94.76,30.941 94.895,30.941 cw(c94.895,30.784) 95.053,30.784 95.053,30.4 ccw(c95.21,30.4) 95.21,30.243 95.345,30.243 ccw(c95.345,30.4) 95.503,30.4 95.503,30.68 cw(c95.66,30.68) 95.66,30.838 95.795,30.838 cw(c95.795,30.68) 95.953,30.68 ccw(c96.153,30.68) 96.153,30.48 96.499,30.48 J15.17
NetJ15_19: J15.19 JMISC_MALE.19 | length 41.5
  TOP w0.2: JMISC_MALE.19@60.797,33.655 77.345,33.655 79.4,31.6 87.2,31.6 90.86,27.94 93.168,27.94 93.268,27.94 ccw(c93.268,28.14) 93.468,28.14 93.468,28.233 cw(c93.626,28.233) 93.626,28.39 93.761,28.39 cw(c93.761,28.233) 93.918,28.233 93.918,27.648 ccw(c94.076,27.648) 94.076,27.49 94.211,27.49 ccw(c94.211,27.648) 94.368,27.648 94.368,28.13 cw(c94.526,28.13) 94.526,28.287 94.661,28.287 cw(c94.661,28.13) 94.818,28.13 94.818,27.74 ccw(c94.976,27.74) 94.976,27.582 95.111,27.582 ccw(c95.111,27.74) 95.268,27.74 cw(c95.468,27.74) 95.468,27.94 96.242,27.94 J15.19
NetJ15_20: J15.20 JMISC_MALE.20 | length 50.6
  TOP w0.2: v1(54.2,33.655) JMISC_MALE.20@56.297,33.655
  BOTTOM w0.2: v1(54.2,33.655) 67.265,33.655 69.02,31.9 94.062,31.9 95.371,30.591 95.371,30.006 96.177,29.2 98.119,29.2 99.092,28.227 99.723,28.227 J15.20
NetJ15_21: J15.21 JMISC_MALE.21 | length 41.5
  TOP w0.2: JMISC_MALE.21@60.797,32.385 74.315,32.385 77.5,29.2 86.153,29.2 89.953,25.4 93.95,25.4 94.05,25.4 ccw(c94.05,25.6) 94.25,25.6 94.25,25.701 cw(c94.407,25.701) 94.407,25.858 94.543,25.858 cw(c94.543,25.701) 94.7,25.701 94.7,25.099 ccw(c94.857,25.099) 94.857,24.942 94.993,24.942 ccw(c94.993,25.099) 95.15,25.099 95.15,25.6 cw(c95.307,25.6) 95.307,25.758 95.443,25.758 cw(c95.443,25.6) 95.6,25.6 ccw(c95.8,25.6) 95.8,25.4 96.862,25.4 J15.21
NetJ15_22: J15.22 JMISC_MALE.22 | length 52.6
  TOP w0.2: v1(54.2,32.385) JMISC_MALE.22@56.297,32.385
  BOTTOM w0.2: v1(54.2,32.385) 68.072,32.385 68.884,31.573 93.927,31.573 95.044,30.456 95.044,27.456 95.81,26.69 98.72,26.69 J15.22
NetJ15_24: J15.24 JMISC_MALE.24 | length 54.5
  TOP w0.2: v1(54.2,31.115) JMISC_MALE.24@56.297,31.115
  BOTTOM w0.2: v1(54.2,31.115) 55.143,32.058 66.642,32.058 68.637,30.063 80.171,30.063 80.834,29.4 92.5,29.4 93,28.9 93,24.8 93.7,24.1 98.77,24.1 J15.24
NetJ15_25: J15.25 JMISC_MALE.37 | length 46
  TOP w0.2: JMISC_MALE.37@60.797,22.225 76.375,22.225 77.7,20.9 77.7,19.5 78.2,19 89.5,19 90.82,20.32 90.891,20.32 90.991,20.32 ccw(c90.991,20.52) 91.191,20.52 91.191,20.706 cw(c91.384,20.706) 91.384,20.898 91.549,20.898 cw(c91.549,20.706) 91.741,20.706 91.741,20.063 ccw(c91.934,20.063) 91.934,19.87 92.099,19.87 ccw(c92.099,20.063) 92.291,20.063 92.291,20.706 cw(c92.484,20.706) 92.484,20.898 92.649,20.898 cw(c92.649,20.706) 92.841,20.706 92.841,20.063 ccw(c93.034,20.063) 93.034,19.87 93.199,19.87 ccw(c93.199,20.063) 93.391,20.063 93.391,20.706 cw(c93.584,20.706) 93.584,20.898 93.749,20.898 cw(c93.749,20.706) 93.941,20.706 93.941,20.063 ccw(c94.134,20.063) 94.134,19.87 94.299,19.87 ccw(c94.299,20.063) 94.491,20.063 94.491,20.706 cw(c94.684,20.706) 94.684,20.898 94.849,20.898 cw(c94.849,20.706) 95.041,20.706 95.041,20.094 ccw(c95.234,20.094) 95.234,19.902 95.399,19.902 ccw(c95.399,20.094) 95.591,20.094 95.591,20.12 cw(c95.791,20.12) 95.791,20.32 96.42,20.32 J15.25
NetJ15_26: J15.26 JMISC_MALE.23 | length 45.7
  TOP w0.2: JMISC_MALE.23@60.797,31.115 v1(62.9,31.115)
  BOTTOM w0.2: v1(62.9,31.115) 64.285,31.115 66.6,28.8 78.2,28.8 80.196,26.804 90.358,26.804 91.3,25.862 91.3,22.4 92.1,21.6 98.73,21.6 J15.26
NetJ15_27: J15.27 JMISC_MALE.39 | length 46
  TOP w0.2: JMISC_MALE.39@60.797,20.955 75.745,20.955 76.7,20 76.7,17.1 77.3,16.5 91.223,16.5 92.503,17.78 92.514,17.78 92.614,17.78 ccw(c92.614,17.98) 92.814,17.98 92.814,18.221 cw(c93.007,18.221) 93.007,18.414 93.172,18.414 cw(c93.172,18.221) 93.364,18.221 93.364,17.523 ccw(c93.557,17.523) 93.557,17.33 93.722,17.33 ccw(c93.722,17.523) 93.914,17.523 93.914,18.221 cw(c94.107,18.221) 94.107,18.414 94.272,18.414 cw(c94.272,18.221) 94.464,18.221 94.464,17.523 ccw(c94.657,17.523) 94.657,17.33 94.822,17.33 ccw(c94.822,17.523) 95.014,17.523 95.014,18.221 cw(c95.207,18.221) 95.207,18.414 95.372,18.414 cw(c95.372,18.221) 95.564,18.221 95.564,17.544 ccw(c95.757,17.544) 95.757,17.351 95.922,17.351 ccw(c95.922,17.544) 96.114,17.544 96.114,17.58 cw(c96.314,17.58) 96.314,17.78 96.618,17.78 J15.27
NetJ15_28: J15.28 JMISC_MALE.25 | length 47.4
  TOP w0.2: JMISC_MALE.25@60.797,29.845 v1(62.9,29.845)
  BOTTOM w0.2: v1(62.9,29.845) 65.055,29.845 66.4,28.5 66.438,28.5 66.465,28.473 78.065,28.473 80.061,26.477 90.223,26.477 90.973,25.727 90.973,20.327 92.3,19 98.79,19 J15.28
NetJ15_29: J15.29 JMISC_MALE.41 | length 46
  TOP w0.2: JMISC_MALE.41@60.797,19.685 74.115,19.685 74.6,19.2 74.6,14.9 75.4,14.1 91.9,14.1 92.974,15.174 93.04,15.24 93.074,15.24 ccw(c93.074,15.44) 93.274,15.44 93.274,15.619 cw(c93.432,15.619) 93.432,15.777 93.567,15.777 cw(c93.567,15.619) 93.724,15.619 93.724,14.948 ccw(c93.882,14.948) 93.882,14.79 94.017,14.79 ccw(c94.017,14.948) 94.174,14.948 94.174,15.619 cw(c94.332,15.619) 94.332,15.777 94.467,15.777 cw(c94.467,15.619) 94.624,15.619 94.624,14.948 ccw(c94.782,14.948) 94.782,14.79 94.917,14.79 ccw(c94.917,14.948) 95.074,14.948 95.074,15.567 cw(c95.232,15.567) 95.232,15.725 95.367,15.725 cw(c95.367,15.567) 95.524,15.567 95.524,15.44 ccw(c95.724,15.44) 95.724,15.24 96.351,15.24 J15.29
NetJ15_31: J15.31 JMISC_MALE.43 | length 46
  TOP w0.2: JMISC_MALE.43@60.797,18.415 72.185,18.415 72.9,17.7 72.9,13 74.4,11.5 91.7,11.5 92.9,12.7 93.2,12.7 93.3,12.7 ccw(c93.3,12.9) 93.5,12.9 93.5,13.02 cw(c93.658,13.02) 93.658,13.178 93.793,13.178 cw(c93.793,13.02) 93.95,13.02 93.95,12.408 ccw(c94.108,12.408) 94.108,12.25 94.243,12.25 ccw(c94.243,12.408) 94.4,12.408 94.4,13.02 cw(c94.558,13.02) 94.558,13.178 94.693,13.178 cw(c94.693,13.02) 94.85,13.02 94.85,12.567 ccw(c95.008,12.567) 95.008,12.41 95.143,12.41 ccw(c95.143,12.567) 95.3,12.567 95.3,12.9 cw(c95.458,12.9) 95.458,13.058 95.593,13.058 cw(c95.593,12.9) 95.75,12.9 ccw(c95.95,12.9) 95.95,12.7 96.4,12.7 J15.31
NetJ15_32: J15.32 JMISC_MALE.46 | length 76.9
  TOP w0.2: v1(54.2,17.145) JMISC_MALE.46@56.297,17.145
  BOTTOM w0.2: v1(54.2,17.145) 53.4,16.345 53.4,15.4 54.1,14.7 60.1,14.7 60.6,14.2 60.6,2.6 62.7,0.5 95.223,0.5 96.005,1.282 96.005,2.598 97.119,3.713 100.713,3.713 101.337,4.337 101.337,12.366 101.004,12.7 J15.32
NetJ15_33: J15.33 JMISC_MALE.45 | length 46
  TOP w0.2: JMISC_MALE.45@60.797,17.145 69.655,17.145 71.05,15.75 71.05,10.25 72.4,8.9 91.9,8.9 93.16,10.16 93.48,10.16 93.58,10.16 ccw(c93.58,10.36) 93.78,10.36 93.78,10.58 cw(c93.938,10.58) 93.938,10.737 94.073,10.737 cw(c94.073,10.58) 94.23,10.58 94.23,9.868 ccw(c94.388,9.868) 94.388,9.71 94.523,9.71 ccw(c94.523,9.868) 94.68,9.868 94.68,10.371 cw(c94.838,10.371) 94.838,10.528 94.973,10.528 cw(c94.973,10.371) 95.13,10.371 95.13,10.36 ccw(c95.33,10.36) 95.33,10.16 96.598,10.16 J15.33
NetJ15_34: J15.34 JMISC_MALE.48 | length 68.9
  TOP w0.2: v1(54.2,15.875) JMISC_MALE.48@56.297,15.875
  BOTTOM w0.2: v1(54.2,15.875) 60.625,15.875 61.8,14.7 61.8,3.2 64.173,0.827 95.088,0.827 95.678,1.417 95.678,8.178 96.314,8.814 99.014,8.814 100.01,9.81 J15.34
NetJ15_35: J15.35 JMISC_MALE.47 | length 46.1
  TOP w0.2: JMISC_MALE.47@60.797,15.875 68.348,15.875 68.7,15.523 68.7,7.1 69.5,6.3 92.6,6.3 93.92,7.62 94.26,7.62 96.3,7.62 J15.35
NetJ15_36: J15.36 JMISC_MALE.50 | length 74.5
  TOP w0.2: JMISC_MALE.50@56.297,14.605 52.605,14.605 52,14 52,1.6 53.2,0.4 101.263,0.4 101.38,0.517 101.38,6.25 J15.36
NetJ15_37: J15.37 JMISC_MALE.49 | length 46.3
  TOP w0.2: JMISC_MALE.49@60.797,14.605 66.095,14.605 67,13.7 67,5.5 68.5,4 93.1,4 94.18,5.08 J15.37
NetJ15_38: J15.38 JMISC_MALE.52 | length 63.9
  TOP w0.2: JMISC_MALE.52@56.297,13.335 53.635,13.335 53.1,12.8 53.1,3.1 55,1.2 98.683,1.2 98.8,1.317 98.8,3.87 J15.38
NetJ15_39: J15.39 JMISC_MALE.51 | length 45.7
  TOP w0.2: JMISC_MALE.51@60.797,13.335 64.665,13.335 65.3,12.7 65.3,5 66.627,3.673 96.337,3.673 J15.39
PF14: J15.16 JMISC_MALE.16 | length 49.2
  TOP w0.2: v1(54.2,36.195) JMISC_MALE.16@56.297,36.195
  BOTTOM w0.2: v1(54.2,36.195) 66.505,36.195 67.703,34.997 78.469,34.997 78.966,34.5 81.767,34.5 81.784,34.483 97.916,34.483 97.933,34.5 98.53,34.5 J15.16
PF15: J15.18 JMISC_MALE.18 | length 49.7
  TOP w0.2: v1(54.2,34.925) JMISC_MALE.18@56.297,34.925
  BOTTOM w0.2: v1(54.2,34.925) 67.312,34.925 67.588,34.65 78.2,34.65 78.694,34.156 94.294,34.156 96.75,31.7 98.159,31.7 99.092,30.767 99.723,30.767 J15.18
PWR_3P3V: J1.4 J14.13 J14.15 JMEDIA_MALE.58 JMEDIA_MALE.60 JMISC_MALE.53 JMISC_MALE.55 | length 7.3
  TOP w0.5: v1(7.4,9.5) 9.409,9.5 JMEDIA_MALE.58@9.434,9.525 ; v1(9.434,7.266) JMEDIA_MALE.60@9.434,8.255 ; JMISC_MALE.55@60.797,10.795 62.895,10.795 v1(62.9,10.8) ; JMISC_MALE.53@60.797,12.065 62.838,12.065 62.873,12.1 v1(62.9,12.1)
VBAT: J1.6 J14.35 JMISC_MALE.60 | length 65
  TOP w0.5: v1(56.297,5.603) JMISC_MALE.60@56.297,8.255
  INNER2 w0.5: v1(56.297,5.603) 71.403,5.603 72.2,6.4 72.2,7 72.82,7.62 J14.35 83.543,8.933 100.624,8.933 v1(101.902,10.212)
  BOTTOM w0.5: v1(101.902,10.212) 101.902,12.025 103.556,13.678 103.556,20.056 J1.6
VCC_PX3_1P8: J1.5 J14.19 J14.21 JMISC_MALE.57 | length 4.1
  TOP w0.5: JMISC_MALE.57@60.797,9.525 v1(62.9,9.525)
  INNER2 w0.5: v1(62.9,9.525) 64.925,9.525
VCOIN: J1.7 J14.39 JMISC_MALE.59 | length 68.6
  TOP w0.5: JMISC_MALE.59@60.797,8.255 62.852,8.255 63.145,7.962 63.145,3.255 64.4,2 79,2 79.54,2.54 J14.39
  INNER2 w0.5: J14.39 83.77,1 100.402,1 101.302,1.9 101.302,8.642 v1(101.902,9.242) ; J1.7 J1.7@106.59,20.09
  BOTTOM w0.5: v1(101.902,9.242) 102.774,10.114 102.774,11.681 104.327,13.233 104.327,19.505 105.142,20.32 J1.7
pads on no net: Fiducial_1.1 Fiducial_2.1

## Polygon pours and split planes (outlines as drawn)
GND on INNER2 "GND_L03" (solid, remove dead copper, pour order 15): 0,1 ccw(c1,1) 1,0 109,0 ccw(c109,1) 110,1 110,52.34 ccw(c109,52.34) 109,53.34 1,53.34 ccw(c1,52.34) 0,52.34
DC_IN on INNER2 "DC_IN" (solid, remove dead copper, pour order 12): 79.194,44.494 82.506,44.494 84.1,42.9 84.1,40.7 103.3,40.7 103.3,34.1 108.8,34.1 108.8,53.34 26.39,53.34 13.3,40.25 13.3,6.25 16.7,6.25 16.7,34.475 32.2,49.975 73.712,49.975
+5V on INNER2 "+5V" (solid, remove dead copper, pour order 13): 91.233,29.767 93.2,27.8 101.6,27.8 103,29.2 108.8,29.2 108.8,33.8 103.1,33.8 103.1,40.5 84.619,40.5 84.619,44.4 78.993,44.4 78.909,44.316 74,49.225 37.404,49.225 37.077,49.552 26.475,38.95 26.475,10.225 54.95,10.225 54.95,12.65 34,12.65 31.025,15.625 31.025,36.212 41.19,46.377 71.56,46.377 77.575,40.362 77.575,37 82.9,37 85,34.9 91.233,34.9
VCC_PX3_1P8 on INNER2 "VCC_PX3_1P8" (solid, remove dead copper, pour order 10): 102.906,25.106 103.9,26.094 108.8,26.094 108.8,23.6 104.4,23.6 104.4,13 100.894,9.494 82.477,9.494 81.484,8.5 64,8.5 64,11.8 75.7,11.8 75.7,29.1 83.5,29.1 83.5,24.3 79.1,24.3 79.1,19 92.184,19 92.184,14.844 101.404,14.844 102.906,16.346
PWR_3P3V on INNER2 "PWR_3P3V" (solid, remove dead copper, pour order 11): 91.017,29.767 93.2,27.584 101.284,27.584 102.9,29.2 108.8,29.2 108.8,26.4 104,26.4 102.6,25 102.6,16.44 101.16,15 92.4,15 92.4,19.3 82.085,19.3 82.085,31.525 63.839,31.525 63.839,5.603 55.75,5.603 55.75,2.05 6.891,2.05 6.891,10.15 10.034,10.15 10.034,6.125 51.675,6.125 51.675,9.925 59.475,9.925 59.475,36.65 83.425,36.65 83.425,34.7 91.017,34.7
GND on TOP "GND_L01" (solid, remove dead copper, pour order 6): 0,1 ccw(c1,1) 1,0 109,0 ccw(c109,1) 110,1 110,52.34 ccw(c109,52.34) 109,53.34 1,53.34 ccw(c1,52.34) 0,52.34
GND on INNER1 "GND_L02" (solid, remove dead copper, pour order 8): 0,1 ccw(c1,1) 1,0 109,0 ccw(c109,1) 110,1 110,52.34 ccw(c109,52.34) 109,53.34 1,53.34 ccw(c1,52.34) 0,52.34
GND on BOTTOM "GND_L04" (solid, remove dead copper, pour order 9): 0,1 ccw(c1,1) 1,0 109,0 ccw(c109,1) 110,1 110,52.34 ccw(c109,52.34) 109,53.34 1,53.34 ccw(c1,52.34) 0,52.34

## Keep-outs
Keep-Out Layer:
  circle w0.05: c104.6,50.17 r2.75
  circle w0.05: c104.6,3.17 r2.75
  circle w0.05: c3,50.17 r2.75
  circle w0.05: c3,3.17 r2.75

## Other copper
BOTTOM:
  text ".version" at 4.749,7.15 h1

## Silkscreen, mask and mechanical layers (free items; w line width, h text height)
Route Tool Path:
  lines w2: 20,-1 1,-1 cw(c1,1) -1,1 -1,52.34 cw(c1,52.34) 1,54.34 20,54.34 ; 25,-1 82.6,-1 ; 25,54.34 82.6,54.34 ; 87.6,-1 106.6,-1 ccw(c106.6,1) 108.6,1 108.6,52.34 ccw(c106.6,52.34) 106.6,54.34 87.6,54.34
Board:
  the board outline again, w0.05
